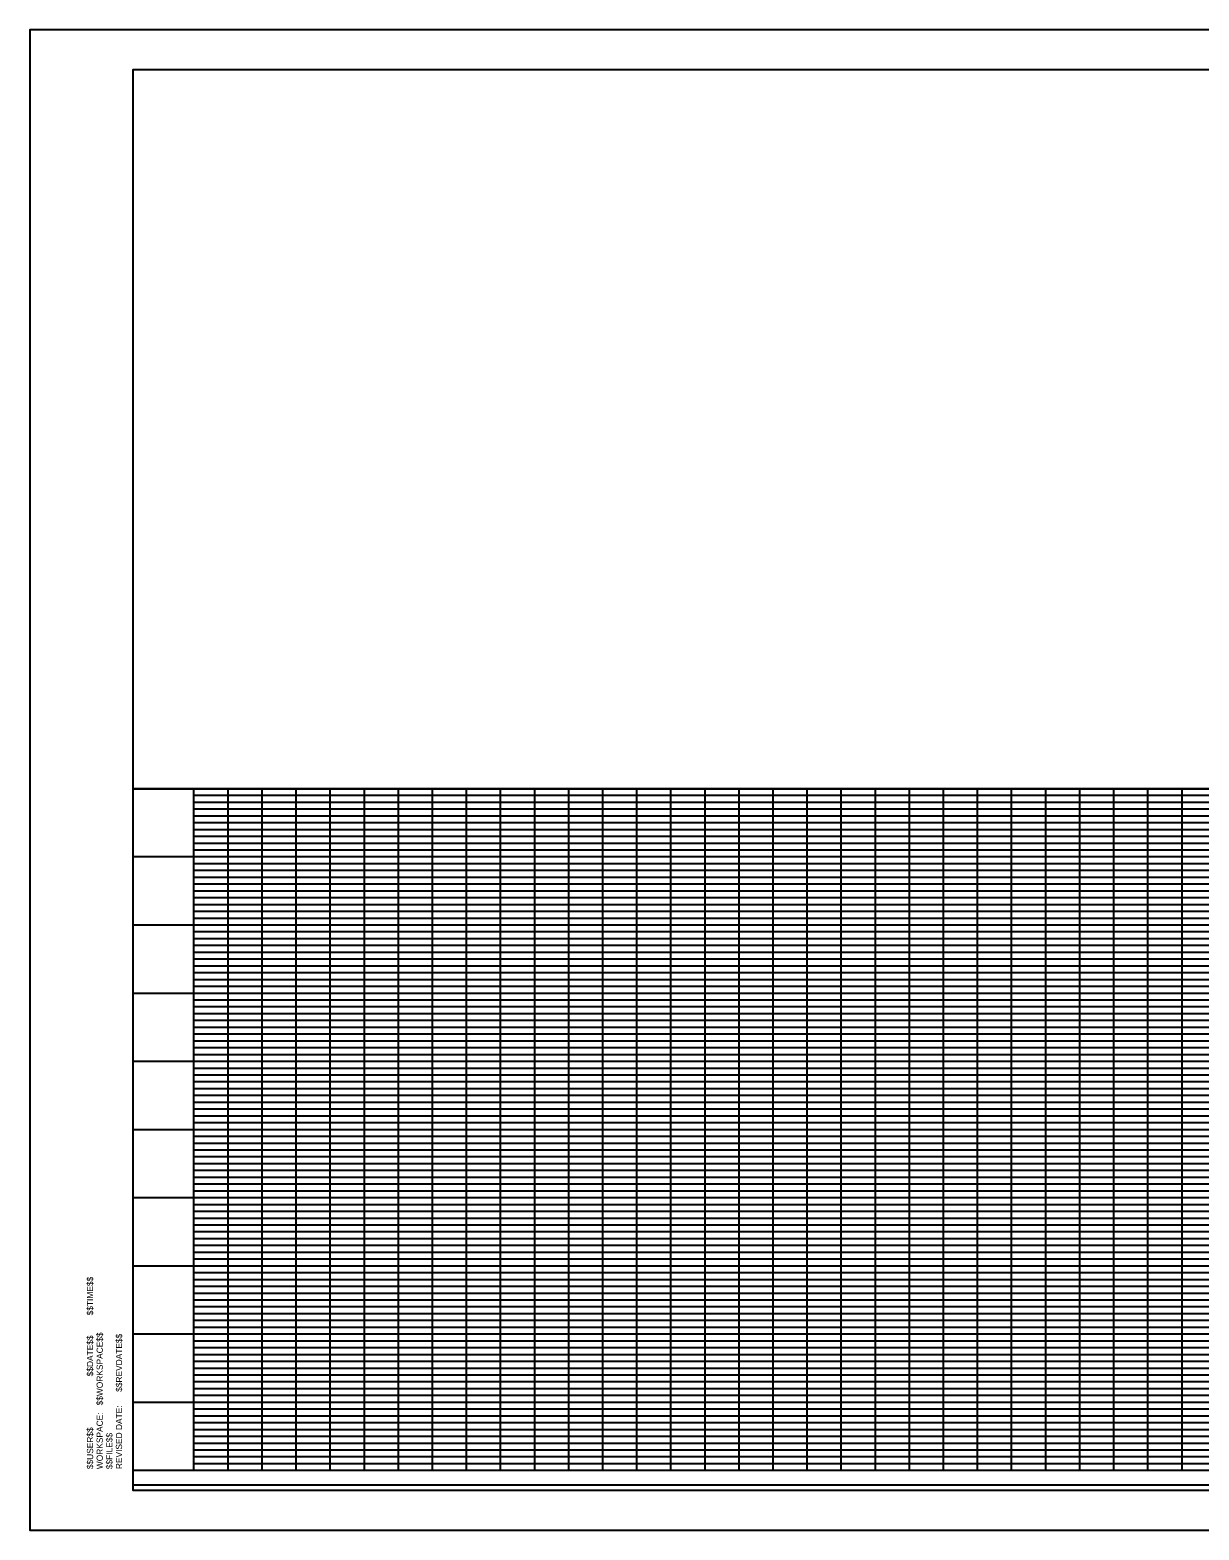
# Model space of a CAD drawing. Extents: x 0 to 1228740, y 0 to 152440.
# Drawn here: x 0 to 17.16, y 0 to 22 of the extents above; entities that cross this region are included whole.
import ezdxf

# ---------------------------------------------------------------- set-up
doc = ezdxf.new("R2010")
doc.units = 0
for name, color, linetype in [('G-TBLK', 7, 'Continuous'), ('R_Border', 7, 'Continuous'), ('R_Grid', 7, 'Continuous'), ('R_No Plot', 7, 'Continuous')]:
    doc.layers.add(name, color=color, linetype=linetype)

msp = doc.modelspace()

# ---------------------------------------------------------------- linework, layer by layer
at = {"layer": 'R_Border'}
for p, q in [((1.516, 21.423), (33.423, 21.423)), ((1.516, 0.577), (1.516, 21.423)), ((33.423, 0.577), (1.516, 0.577))]:
    msp.add_line(p, q, dxfattribs=at)
msp.add_lwpolyline([(34, 22), (0, 22), (0, 0), (34, 0)], close=True, dxfattribs=at)
at = {"layer": 'R_Grid'}
for p, q in [((33.423, 10.871), (1.516, 10.871)), ((2.407, 0.871), (2.407, 10.871)), ((2.907, 0.871), (2.907, 10.871)), ((3.407, 0.871), (3.407, 10.871)), ((3.907, 0.871), (3.907, 10.871)), ((4.407, 0.871), (4.407, 10.871)), ((4.907, 0.871), (4.907, 10.871)), ((5.407, 0.871), (5.407, 10.871)), ((5.907, 0.871), (5.907, 10.871)), ((6.407, 0.871), (6.407, 10.871)), ((6.907, 0.871), (6.907, 10.871)), ((7.407, 0.871), (7.407, 10.871)), ((7.907, 0.871), (7.907, 10.871)), ((8.407, 0.871), (8.407, 10.871)), ((8.907, 0.871), (8.907, 10.871)), ((9.407, 0.871), (9.407, 10.871)), ((9.907, 0.871), (9.907, 10.871)), ((10.407, 0.871), (10.407, 10.871)), ((10.907, 0.871), (10.907, 10.871)), ((11.407, 0.871), (11.407, 10.871)), ((11.907, 0.871), (11.907, 10.871)), ((12.407, 0.871), (12.407, 10.871)), ((12.907, 0.871), (12.907, 10.871)), ((13.407, 0.871), (13.407, 10.871)), ((13.907, 0.871), (13.907, 10.871)), ((14.407, 0.871), (14.407, 10.871)), ((14.907, 0.871), (14.907, 10.871)), ((15.407, 0.871), (15.407, 10.871)), ((15.907, 0.871), (15.907, 10.871)), ((16.407, 0.871), (16.407, 10.871)), ((16.907, 0.871), (16.907, 10.871)), ((32.407, 10.771), (2.407, 10.771)), ((32.407, 10.671), (2.407, 10.671)), ((32.407, 10.571), (2.407, 10.571)), ((32.407, 10.471), (2.407, 10.471)), ((32.407, 10.371), (2.407, 10.371)), ((32.407, 10.271), (2.407, 10.271)), ((32.407, 10.171), (2.407, 10.171)), ((32.407, 10.071), (2.407, 10.071)), ((32.407, 9.971), (2.407, 9.971)), ((33.423, 9.871), (1.516, 9.871)), ((32.407, 9.771), (2.407, 9.771)), ((32.407, 9.671), (2.407, 9.671)), ((32.407, 9.571), (2.407, 9.571)), ((32.407, 9.471), (2.407, 9.471)), ((32.407, 9.371), (2.407, 9.371)), ((32.407, 9.271), (2.407, 9.271)), ((32.407, 9.171), (2.407, 9.171)), ((32.407, 9.071), (2.407, 9.071)), ((33.423, 8.871), (1.516, 8.871)), ((32.407, 8.971), (2.407, 8.971)), ((32.407, 8.771), (2.407, 8.771)), ((32.407, 8.671), (2.407, 8.671)), ((32.407, 8.571), (2.407, 8.571)), ((32.407, 8.471), (2.407, 8.471)), ((32.407, 8.371), (2.407, 8.371)), ((32.407, 8.271), (2.407, 8.271)), ((32.407, 8.171), (2.407, 8.171)), ((32.407, 8.071), (2.407, 8.071)), ((32.407, 7.971), (2.407, 7.971)), ((33.423, 7.871), (1.516, 7.871)), ((32.407, 7.771), (2.407, 7.771)), ((32.407, 7.671), (2.407, 7.671)), ((32.407, 7.571), (2.407, 7.571)), ((32.407, 7.471), (2.407, 7.471)), ((32.407, 7.371), (2.407, 7.371)), ((32.407, 7.271), (2.407, 7.271)), ((32.407, 7.171), (2.407, 7.171)), ((32.407, 7.071), (2.407, 7.071)), ((33.423, 6.871), (1.516, 6.871)), ((32.407, 6.971), (2.407, 6.971)), ((32.407, 6.771), (2.407, 6.771)), ((32.407, 6.671), (2.407, 6.671)), ((32.407, 6.571), (2.407, 6.571)), ((32.407, 6.471), (2.407, 6.471)), ((32.407, 6.371), (2.407, 6.371)), ((32.407, 6.271), (2.407, 6.271)), ((32.407, 6.171), (2.407, 6.171)), ((32.407, 6.071), (2.407, 6.071)), ((32.407, 5.971), (2.407, 5.971)), ((33.423, 5.871), (1.516, 5.871)), ((32.407, 5.771), (2.407, 5.771)), ((32.407, 5.671), (2.407, 5.671)), ((32.407, 5.571), (2.407, 5.571)), ((32.407, 5.471), (2.407, 5.471)), ((32.407, 5.371), (2.407, 5.371)), ((32.407, 5.271), (2.407, 5.271)), ((32.407, 5.171), (2.407, 5.171)), ((32.407, 5.071), (2.407, 5.071)), ((33.423, 4.871), (1.516, 4.871)), ((32.407, 4.971), (2.407, 4.971)), ((32.407, 4.771), (2.407, 4.771)), ((32.407, 4.671), (2.407, 4.671)), ((32.407, 4.571), (2.407, 4.571)), ((32.407, 4.471), (2.407, 4.471)), ((32.407, 4.371), (2.407, 4.371)), ((32.407, 4.271), (2.407, 4.271)), ((32.407, 4.171), (2.407, 4.171)), ((32.407, 4.071), (2.407, 4.071)), ((32.407, 3.971), (2.407, 3.971)), ((33.423, 3.871), (1.516, 3.871)), ((32.407, 3.771), (2.407, 3.771)), ((32.407, 3.671), (2.407, 3.671)), ((32.407, 3.571), (2.407, 3.571)), ((32.407, 3.471), (2.407, 3.471)), ((32.407, 3.371), (2.407, 3.371)), ((32.407, 3.271), (2.407, 3.271)), ((32.407, 3.171), (2.407, 3.171)), ((33.423, 2.871), (1.516, 2.871)), ((32.407, 3.071), (2.407, 3.071)), ((32.407, 2.971), (2.407, 2.971)), ((32.407, 2.771), (2.407, 2.771)), ((32.407, 2.671), (2.407, 2.671)), ((32.407, 2.571), (2.407, 2.571)), ((32.407, 2.471), (2.407, 2.471)), ((32.407, 2.371), (2.407, 2.371)), ((32.407, 2.271), (2.407, 2.271)), ((32.407, 2.171), (2.407, 2.171)), ((32.407, 2.071), (2.407, 2.071)), ((33.423, 1.871), (1.516, 1.871)), ((32.407, 1.971), (2.407, 1.971)), ((32.407, 1.771), (2.407, 1.771)), ((32.407, 1.671), (2.407, 1.671)), ((32.407, 1.571), (2.407, 1.571)), ((32.407, 1.471), (2.407, 1.471)), ((32.407, 1.371), (2.407, 1.371)), ((32.407, 1.271), (2.407, 1.271)), ((32.407, 1.171), (2.407, 1.171)), ((32.407, 1.071), (2.407, 1.071)), ((32.407, 0.971), (2.407, 0.971)), ((33.423, 0.871), (1.516, 0.871))]:
    msp.add_line(p, q, dxfattribs=at)
at = {"layer": 'R_No Plot'}
for points in [[(33.423, 17.405), (33.423, 10.871), (1.516, 10.871), (1.516, 21.423), (25.197, 21.423), (25.197, 20.435), (28.749, 20.435), (28.749, 20.078), (29.113, 20.078), (29.113, 20.143), (30.667, 20.143)], [(33.423, 17.405), (33.423, 0.657), (1.516, 0.657), (1.516, 21.423), (25.197, 21.423), (25.197, 20.435), (28.749, 20.435), (28.749, 20.078), (29.113, 20.078), (29.113, 20.143), (30.667, 20.143)]]:
    msp.add_lwpolyline(points, dxfattribs=at)
msp.add_lwpolyline([(1.516, 10.871), (33.423, 10.871), (33.423, 0.577), (1.516, 0.577)], close=True, dxfattribs=at)

# ---------------------------------------------------------------- texts
at = {"layer": 'G-TBLK'}
for s, p in [('$$TIME$$', (0.927, 3.148)), ('$$WORKSPACE$$', (1.069, 1.827)), ('$$REVDATE$$', (1.352, 2.026)), ('$$DATE$$', (0.927, 2.254)), ('REVISED DATE:', (1.352, 0.893)), ('WORKSPACE:', (1.069, 0.892)), ('$$USER$$', (0.927, 0.892)), ('$$FILE$$', (1.211, 0.892))]:
    msp.add_text(s, height=0.0918, rotation=90, dxfattribs=at).set_placement(p)

doc.saveas('drawing.dxf')
